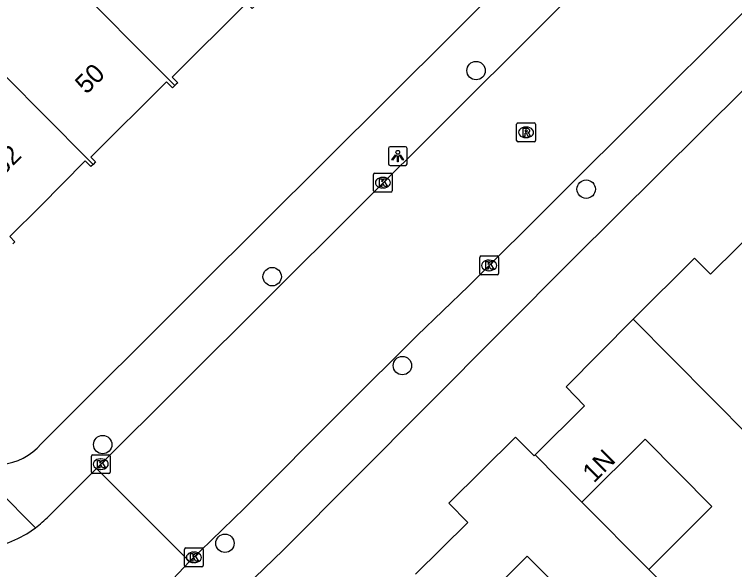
# Model space of a CAD drawing. Extents: x 159222 to 160346, y 381249 to 382166.
# Drawn here: x 159998.63 to 160036.91, y 381780.83 to 381810.32 of the extents above; entities that cross this region are included whole.
import ezdxf

# ---------------------------------------------------------------- set-up
doc = ezdxf.new("R2010")
doc.units = 0
for name, color, linetype in [('IMGEO_Boom', 7, 'Continuous'), ('IMGEO_Kolk', 7, 'Continuous'), ('IMGEO_Lichtpunt', 7, 'Continuous'), ('IMGEO_Pand', 7, 'Continuous'), ('IMGEO_Pand_nummerreeks', 7, 'Continuous'), ('IMGEO_Rijbaan_lokaal_open', 7, 'Continuous'), ('IMGEO_Rioolput', 7, 'Continuous'), ('IMGEO_Voetpad_open', 7, 'Continuous')]:
    doc.layers.add(name, color=color, linetype=linetype)

msp = doc.modelspace()

# ---------------------------------------------------------------- linework, layer by layer
at = {"layer": 'IMGEO_Boom'}
for centre in [(160023.171, 381807.335), (160029.021, 381801.038), (160012.332, 381796.389), (160019.256, 381791.665), (160003.323, 381787.47), (160009.823, 381782.229)]:
    msp.add_circle(centre, 0.489, dxfattribs=at)
at = {"layer": 'IMGEO_Kolk'}
for p, q in [((160017.716, 381800.957), (160017.716, 381801.809)), ((160017.791, 381801.883), (160018.643, 381801.883)), ((160018.204, 381801.663), (160018.229, 381801.663)), ((160018.717, 381801.809), (160018.717, 381800.957)), ((160018.643, 381800.883), (160017.791, 381800.883)), ((160018.227, 381801.103), (160018.202, 381801.103)), ((160023.362, 381796.562), (160023.362, 381797.414)), ((160023.437, 381797.488), (160024.289, 381797.488)), ((160024.363, 381797.414), (160024.363, 381796.562)), ((160023.85, 381797.268), (160023.875, 381797.268)), ((160023.873, 381796.708), (160023.848, 381796.708)), ((160024.289, 381796.488), (160023.437, 381796.488)), ((160002.72, 381786.005), (160002.72, 381786.857)), ((160002.795, 381786.931), (160003.647, 381786.931)), ((160003.208, 381786.711), (160003.233, 381786.711)), ((160003.721, 381786.857), (160003.721, 381786.005)), ((160003.647, 381785.931), (160002.795, 381785.931)), ((160003.231, 381786.151), (160003.206, 381786.151)), ((160007.67, 381781.054), (160007.67, 381781.906)), ((160007.745, 381781.98), (160008.597, 381781.98)), ((160008.158, 381781.76), (160008.183, 381781.76)), ((160008.671, 381781.906), (160008.671, 381781.054)), ((160008.597, 381780.98), (160007.745, 381780.98)), ((160008.181, 381781.2), (160008.156, 381781.2))]:
    msp.add_line(p, q, dxfattribs=at)
for points in [[(160017.716, 381800.957), (160017.716, 381801.809)], [(160017.791, 381801.883), (160018.643, 381801.883)], [(160018.717, 381801.809), (160018.717, 381800.957)], [(160018.037, 381801.583), (160018.16, 381801.583), (160018.16, 381801.432), (160018.29, 381801.583), (160018.454, 381801.583), (160018.308, 381801.432), (160018.461, 381801.183), (160018.309, 381801.183), (160018.224, 381801.347), (160018.16, 381801.28), (160018.16, 381801.183), (160018.037, 381801.183), (160018.037, 381801.583)], [(160018.643, 381800.883), (160017.791, 381800.883)], [(160023.362, 381796.562), (160023.362, 381797.414)], [(160023.437, 381797.488), (160024.289, 381797.488)], [(160024.363, 381797.414), (160024.363, 381796.562)], [(160023.683, 381797.188), (160023.806, 381797.188), (160023.806, 381797.037), (160023.936, 381797.188), (160024.1, 381797.188), (160023.954, 381797.037), (160024.107, 381796.788), (160023.955, 381796.788), (160023.87, 381796.952), (160023.806, 381796.885), (160023.806, 381796.788), (160023.683, 381796.788), (160023.683, 381797.188)], [(160024.289, 381796.488), (160023.437, 381796.488)], [(160002.72, 381786.005), (160002.72, 381786.857)], [(160002.795, 381786.931), (160003.647, 381786.931)], [(160003.721, 381786.857), (160003.721, 381786.005)], [(160003.041, 381786.631), (160003.164, 381786.631), (160003.164, 381786.48), (160003.294, 381786.631), (160003.458, 381786.631), (160003.312, 381786.48), (160003.465, 381786.231), (160003.313, 381786.231), (160003.228, 381786.395), (160003.164, 381786.328), (160003.164, 381786.231), (160003.041, 381786.231), (160003.041, 381786.631)], [(160003.647, 381785.931), (160002.795, 381785.931)], [(160007.67, 381781.054), (160007.67, 381781.906)], [(160007.745, 381781.98), (160008.597, 381781.98)], [(160008.671, 381781.906), (160008.671, 381781.054)], [(160007.991, 381781.68), (160008.114, 381781.68), (160008.114, 381781.529), (160008.244, 381781.68), (160008.408, 381781.68), (160008.262, 381781.529), (160008.415, 381781.28), (160008.263, 381781.28), (160008.178, 381781.444), (160008.114, 381781.377), (160008.114, 381781.28), (160007.991, 381781.28), (160007.991, 381781.68)], [(160008.597, 381780.98), (160007.745, 381780.98)]]:
    msp.add_lwpolyline(points, dxfattribs=at)
for centre, start, end in [((160017.793, 381801.807), 91.552, 178.448), ((160017.793, 381801.807), 91.552, 178.448), ((160018.641, 381801.807), 1.552, 88.448), ((160018.641, 381801.807), 1.552, 88.448), ((160017.793, 381800.959), 181.552, 268.448), ((160017.793, 381800.959), 181.552, 268.448), ((160018.641, 381800.959), 271.552, 358.448), ((160018.641, 381800.959), 271.552, 358.448), ((160023.439, 381797.412), 91.552, 178.448), ((160023.439, 381797.412), 91.552, 178.448), ((160024.287, 381797.412), 1.552, 88.448), ((160024.287, 381797.412), 1.552, 88.448), ((160023.439, 381796.564), 181.552, 268.448), ((160023.439, 381796.564), 181.552, 268.448), ((160024.287, 381796.564), 271.552, 358.448), ((160024.287, 381796.564), 271.552, 358.448), ((160002.797, 381786.855), 91.552, 178.448), ((160002.797, 381786.855), 91.552, 178.448), ((160003.645, 381786.855), 1.552, 88.448), ((160003.645, 381786.855), 1.552, 88.448), ((160002.797, 381786.007), 181.552, 268.448), ((160002.797, 381786.007), 181.552, 268.448), ((160003.645, 381786.007), 271.552, 358.448), ((160003.645, 381786.007), 271.552, 358.448), ((160007.747, 381781.904), 91.552, 178.448), ((160007.747, 381781.904), 91.552, 178.448), ((160008.595, 381781.904), 1.552, 88.448), ((160008.595, 381781.904), 1.552, 88.448), ((160007.747, 381781.056), 181.552, 268.448), ((160007.747, 381781.056), 181.552, 268.448), ((160008.595, 381781.056), 271.552, 358.448), ((160008.595, 381781.056), 271.552, 358.448)]:
    msp.add_arc(centre, 0.0765, start, end, dxfattribs=at)
for centre, major_axis, ratio, start_param, end_param in [((160018.203, 381801.383), (-0.387, 0.002), 0.722429, 4.712389, 7.853982), ((160018.228, 381801.383), (-0.39, 0.002), 0.717154, 1.570796, 4.712389), ((160023.849, 381796.988), (-0.387, 0.002), 0.722429, 4.712389, 7.853982), ((160023.874, 381796.988), (-0.39, 0.002), 0.717154, 1.570796, 4.712389), ((160003.207, 381786.431), (-0.387, 0.002), 0.722429, 4.712389, 7.853982), ((160003.232, 381786.431), (-0.39, 0.002), 0.717154, 1.570796, 4.712389), ((160008.157, 381781.48), (-0.387, 0.002), 0.722429, 4.712389, 7.853982), ((160008.182, 381781.48), (-0.39, 0.002), 0.717154, 1.570796, 4.712389)]:
    msp.add_ellipse(centre, major_axis=major_axis, ratio=ratio, start_param=start_param, end_param=end_param, dxfattribs=at)
at = {"layer": 'IMGEO_Lichtpunt'}
for p, q in [((160018.508, 381803.199), (160018.508, 381802.392)), ((160018.508, 381803.199), (160018.508, 381802.392)), ((160019.41, 381803.294), (160018.602, 381803.294)), ((160019.41, 381803.294), (160018.602, 381803.294)), ((160019.504, 381802.392), (160019.504, 381803.199)), ((160019.504, 381802.392), (160019.504, 381803.199)), ((160018.602, 381802.298), (160019.41, 381802.298)), ((160018.602, 381802.298), (160019.41, 381802.298))]:
    msp.add_line(p, q, dxfattribs=at)
for points in [[(160018.882, 381802.863), (160018.921, 381802.835), (160018.733, 381802.573), (160018.695, 381802.6), (160018.882, 381802.863)], [(160018.984, 381802.815), (160019.031, 381802.815), (160019.031, 381802.493), (160018.984, 381802.493), (160018.984, 381802.815)], [(160019.094, 381802.835), (160019.132, 381802.862), (160019.319, 381802.6), (160019.28, 381802.572), (160019.094, 381802.835)]]:
    msp.add_lwpolyline(points, dxfattribs=at)
msp.add_circle((160019.007, 381802.997), 0.0994, dxfattribs=at)
for centre, start, end in [((160018.602, 381803.199), 90, 180), ((160018.602, 381803.199), 90, 180), ((160019.41, 381803.199), 0, 90), ((160019.41, 381803.199), 0, 90), ((160018.602, 381802.392), 180, 270), ((160018.602, 381802.392), 180, 270), ((160019.41, 381802.392), 270, 0), ((160019.41, 381802.392), 270, 360)]:
    msp.add_arc(centre, 0.0946, start, end, dxfattribs=at)
at = {"layer": 'IMGEO_Pand'}
for points in [[(160001.226, 381812.517), (160007.163, 381806.547)], [(160011.401, 381810.773), (160011.27, 381810.642), (160010.979, 381810.935), (160007.018, 381806.985), (160007.309, 381806.693), (160007.234, 381806.618), (160007.163, 381806.547)], [(159994.679, 381810.489), (159996.907, 381808.288), (160000, 381805.186), (160002.813, 381802.35)], [(160007.163, 381806.547), (160007.029, 381806.413), (160006.708, 381806.736), (160002.694, 381802.732), (160002.944, 381802.481), (160002.813, 381802.35)], [(160002.813, 381802.35), (160002.696, 381802.233), (160002.395, 381802.536), (160000, 381800.124), (159998.386, 381798.515), (159998.654, 381798.246), (159998.544, 381798.137)], [(160031.518, 381794.127), (160034.782, 381797.369), (160035.628, 381796.518), (160038.545, 381799.415), (160039.391, 381798.564), (160041.33, 381800.49)], [(160026.312, 381786.922), (160028.936, 381789.525), (160027.951, 381790.536), (160031.518, 381794.127)], [(160031.518, 381794.127), (160041.879, 381783.695)], [(160019.955, 381780.587), (160022.732, 381783.332), (160021.728, 381784.351), (160025.265, 381787.869), (160026.26, 381786.87), (160026.312, 381786.922)], [(160028.783, 381784.421), (160032.147, 381787.762), (160035.706, 381784.178), (160032.342, 381780.838)], [(160028.783, 381784.421), (160026.312, 381786.922)], [(160032.342, 381780.838), (160028.783, 381784.421)], [(160022.421, 381778.104), (160025.893, 381781.552), (160029.453, 381777.968), (160025.98, 381774.52)], [(160035.655, 381777.502), (160032.342, 381780.838)]]:
    msp.add_lwpolyline(points, dxfattribs=at)
at = {"layer": 'IMGEO_Rijbaan_lokaal_open'}
for points in [[(160002.99, 381786.2), (160012.11, 381795.292), (160116.933, 381899.648), (160120.802, 381903.57), (160121.409, 381904.226), (160123.621, 381906.761), (160125.502, 381909.146), (160137.982, 381924.966), (160137.985, 381924.969)], [(160116.227, 381888.855), (160106.101, 381878.782), (160096.927, 381869.656), (160085.354, 381858.143), (160080.535, 381853.35), (160070.584, 381843.451), (160069.21, 381842.087), (160064.536, 381837.45), (160052.791, 381825.786), (160048.168, 381821.179), (160036.822, 381809.873), (160032.195, 381805.263), (160022.766, 381795.885), (160020.046, 381793.267), (160016.183, 381789.42), (160010.858, 381784.097), (160007.94, 381781.256)], [(160000.461, 381783.668), (160002.99, 381786.2)], [(160007.94, 381781.256), (160002.99, 381786.2)], [(160007.94, 381781.256), (160006.471, 381779.705), (160005.464, 381778.598)]]:
    msp.add_lwpolyline(points, dxfattribs=at)
for centre, radius, start, end in [((159996.024, 381788.032), 6.223, 306.74, 315.4725), ((159996.178, 381787.86), 5.993, 225.4357, 306.5439)]:
    msp.add_arc(centre, radius, start, end, dxfattribs=at)
at = {"layer": 'IMGEO_Rioolput'}
for p, q in [((160025.324, 381803.63), (160025.324, 381804.482)), ((160025.399, 381804.556), (160026.251, 381804.556)), ((160025.812, 381804.336), (160025.837, 381804.336)), ((160026.325, 381804.482), (160026.325, 381803.63)), ((160026.251, 381803.556), (160025.399, 381803.556)), ((160025.835, 381803.776), (160025.81, 381803.776))]:
    msp.add_line(p, q, dxfattribs=at)
for points in [[(160025.324, 381803.63), (160025.324, 381804.482)], [(160025.399, 381804.556), (160026.251, 381804.556)], [(160026.325, 381804.482), (160026.325, 381803.63)], [(160025.913, 381804.254), (160025.661, 381804.256), (160025.661, 381803.856)], [(160025.661, 381803.856), (160025.785, 381803.856), (160025.785, 381804.018), (160025.796, 381804.018)], [(160025.839, 381804.175), (160025.785, 381804.175), (160025.785, 381804.094)], [(160025.785, 381804.094), (160025.837, 381804.094)], [(160025.843, 381803.989), (160025.914, 381803.856), (160026.054, 381803.856), (160025.989, 381803.982)], [(160026.251, 381803.556), (160025.399, 381803.556)]]:
    msp.add_lwpolyline(points, dxfattribs=at)
for centre, radius, start, end in [((160025.401, 381804.48), 0.0765, 91.552, 178.448), ((160025.401, 381804.48), 0.0765, 91.552, 178.448), ((160026.249, 381804.48), 0.0765, 1.552, 88.448), ((160026.249, 381804.48), 0.0765, 1.552, 88.448), ((160025.795, 381803.965), 0.0533, 26.0293, 88.6989), ((160025.821, 381804.283), 0.19, 274.7715, 282.9687), ((160025.845, 381804.079), 0.0964, 77.0061, 93.1865), ((160025.859, 381804.136), 0.0378, 276.6634, 79.6772), ((160025.912, 381804.144), 0.109, 350.3612, 89.416), ((160025.91, 381804.144), 0.112, 277.5842, 350.9817), ((160025.894, 381803.929), 0.108, 29.5134, 73.7905), ((160025.401, 381803.632), 0.0765, 181.552, 268.448), ((160025.401, 381803.632), 0.0765, 181.552, 268.448), ((160026.249, 381803.632), 0.0765, 271.552, 358.448), ((160026.249, 381803.632), 0.0765, 271.552, 358.448)]:
    msp.add_arc(centre, radius, start, end, dxfattribs=at)
for centre, major_axis, ratio, start_param, end_param in [((160025.811, 381804.056), (-0.387, 0.002), 0.722429, 4.712389, 7.853982), ((160025.836, 381804.056), (-0.39, 0.002), 0.717154, 1.570796, 4.712389)]:
    msp.add_ellipse(centre, major_axis=major_axis, ratio=ratio, start_param=start_param, end_param=end_param, dxfattribs=at)
at = {"layer": 'IMGEO_Voetpad_open'}
for points in [[(160108.118, 381876.482), (160028.327, 381797.338), (160012.912, 381781.871), (160008.385, 381777.496)], [(160038.791, 381826.068), (160008.419, 381795.853), (160000.048, 381787.508)], [(159995.728, 381787.091), (159999.747, 381783.045)]]:
    msp.add_lwpolyline(points, dxfattribs=at)
msp.add_arc((159997.673, 381789.523), 3.114, 231.3385, 319.6886, dxfattribs=at)

# ---------------------------------------------------------------- texts
at = {"layer": 'IMGEO_Pand_nummerreeks'}
for s, rotation, p in [('50', 44.6725, (160002.455, 381806.039)), ('52', 45.0856, (159998.021, 381801.717)), ('1N', 44.7666, (160029.428, 381785.393))]:
    msp.add_text(s, height=1, rotation=rotation, dxfattribs=at).set_placement(p)

doc.saveas('drawing.dxf')
